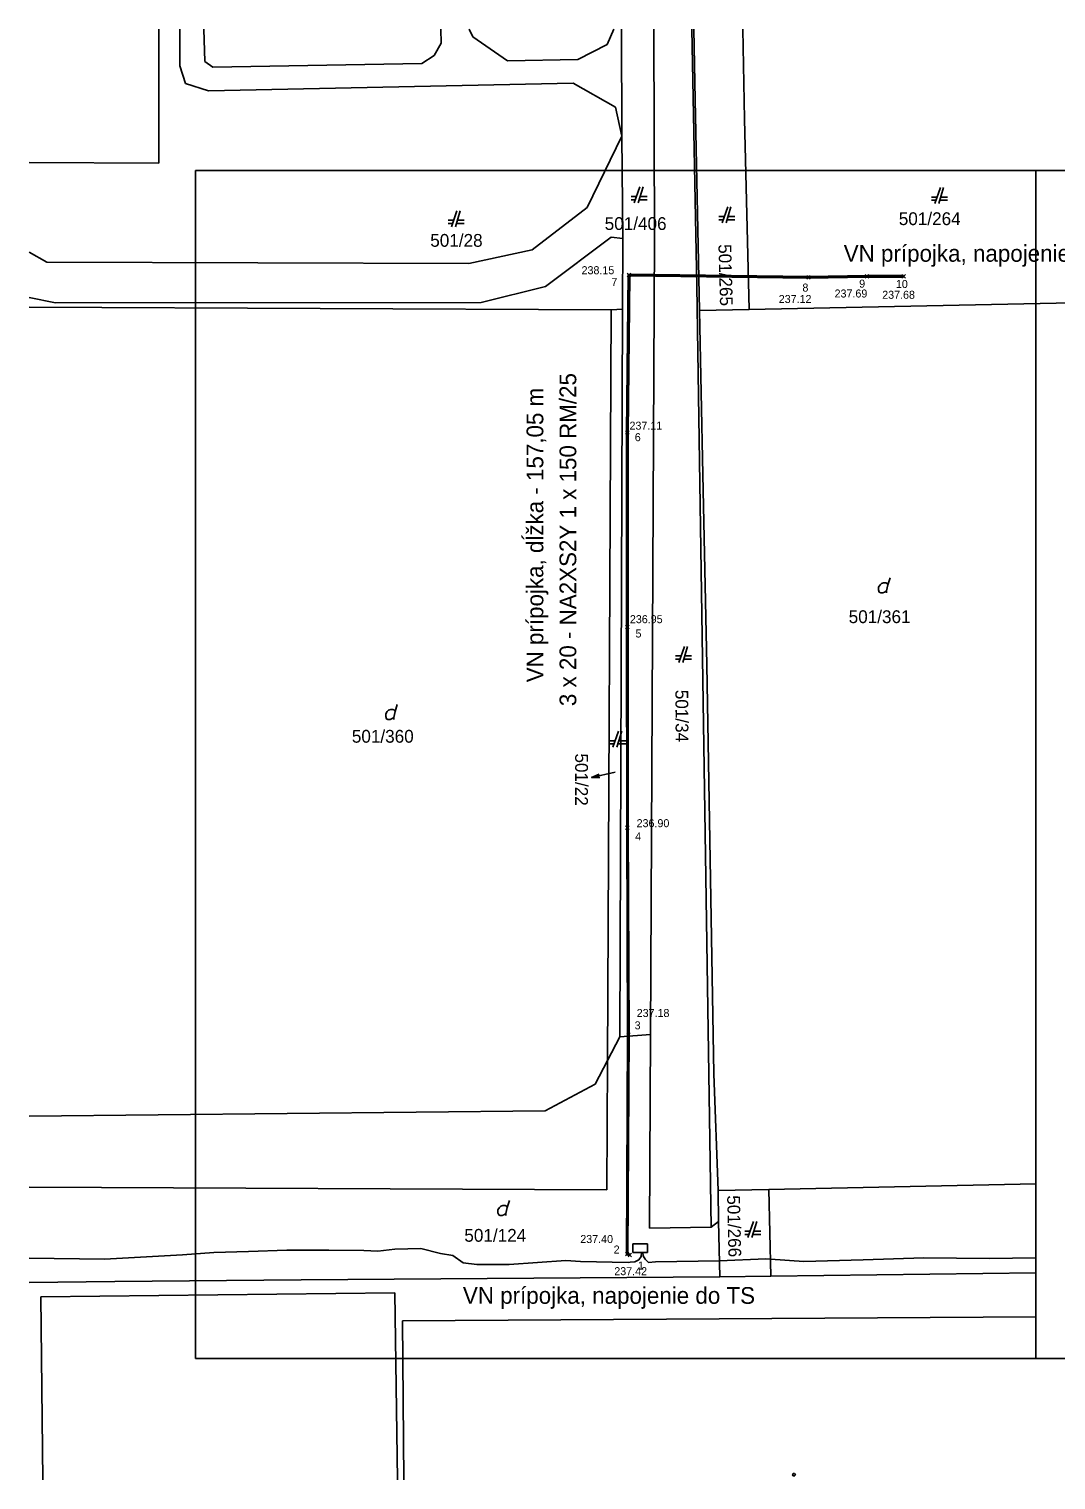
# Model space of a CAD drawing. Extents: x -264024 to -263772, y -1242343 to -1242155.
# Drawn here: x -264023.6 to -263895.2, y -1242343 to -1242161.7 of the extents above; entities that cross this region are included whole.
import ezdxf

# ---------------------------------------------------------------- set-up
doc = ezdxf.new("R2010")
doc.units = 0
for name, color, linetype in [('Default', 7, 'Continuous'), ('Kataster', 7, 'Continuous'), ('Kábelová chránička', 7, 'Continuous'), ('Meraný bod', 7, 'Continuous'), ('Nadmorská výška', 7, 'Continuous'), ('VN kabel', 7, 'Continuous'), ('VN vedenie popis', 7, 'Continuous'), ('Číslo meraného bodu', 7, 'Continuous')]:
    doc.layers.add(name, color=color, linetype=linetype)

msp = doc.modelspace()

# ---------------------------------------------------------------- linework, layer by layer
at = {"layer": 'Default'}
for points in [[(-264002.76, -1242179.33), (-263897.76, -1242179.33), (-263897.76, -1242327.83), (-264002.76, -1242327.83)], [(-263897.76, -1242179.33), (-263792.76, -1242179.33), (-263792.76, -1242327.83), (-263897.76, -1242327.83)]]:
    msp.add_lwpolyline(points, close=True, dxfattribs=at)
at = {"layer": 'Kataster'}
for p, q in [((-264007.36, -1242161.66), (-264007.34, -1242178.42)), ((-264007.34, -1242178.42), (-264007.36, -1242161.66)), ((-264004.74, -1242161.66), (-264004.75, -1242166.25)), ((-264004.75, -1242166.25), (-264004.74, -1242161.66)), ((-264001.62, -1242165.72), (-264001.72, -1242161.66)), ((-264001.72, -1242161.66), (-264001.62, -1242165.72)), ((-263972.1, -1242161.66), (-263972.09, -1242163.43)), ((-263972.09, -1242163.43), (-263972.1, -1242161.66)), ((-263968.11, -1242162.65), (-263968.57, -1242161.66)), ((-263968.57, -1242161.66), (-263968.11, -1242162.65)), ((-263963.77, -1242165.63), (-263968.11, -1242162.65)), ((-263968.11, -1242162.65), (-263963.77, -1242165.63)), ((-263950.51, -1242161.66), (-263951.34, -1242163.61)), ((-263951.34, -1242163.61), (-263950.51, -1242161.66)), ((-263949.49, -1242175.05), (-263949.54, -1242161.66)), ((-263949.54, -1242161.66), (-263949.49, -1242175.05)), ((-263945.5, -1242161.66), (-263945.41, -1242187.87)), ((-263945.41, -1242187.87), (-263945.5, -1242161.66)), ((-263940.75, -1242161.66), (-263940.13, -1242193.8)), ((-263940.13, -1242193.8), (-263940.75, -1242161.66)), ((-263940.34, -1242170.51), (-263940.5, -1242161.66)), ((-263940.5, -1242161.66), (-263940.34, -1242170.51)), ((-263934.15, -1242172.94), (-263934.38, -1242161.66)), ((-263934.38, -1242161.66), (-263934.15, -1242172.94)), ((-263972.93, -1242164.99), (-263974.51, -1242165.96)), ((-263974.51, -1242165.96), (-263972.93, -1242164.99)), ((-263972.09, -1242163.43), (-263972.93, -1242164.99)), ((-263972.93, -1242164.99), (-263972.09, -1242163.43)), ((-263951.34, -1242163.61), (-263955.01, -1242165.46)), ((-263955.01, -1242165.46), (-263951.34, -1242163.61)), ((-264004.75, -1242166.25), (-264004.02, -1242168.46)), ((-264004.02, -1242168.46), (-264004.75, -1242166.25)), ((-264000.63, -1242166.44), (-264001.62, -1242165.72)), ((-264001.62, -1242165.72), (-264000.63, -1242166.44)), ((-263974.51, -1242165.96), (-264000.63, -1242166.44)), ((-264000.63, -1242166.44), (-263974.51, -1242165.96)), ((-263955.01, -1242165.46), (-263963.77, -1242165.63)), ((-263963.77, -1242165.63), (-263955.01, -1242165.46)), ((-264004.02, -1242168.46), (-264001.16, -1242169.4)), ((-264001.16, -1242169.4), (-264004.02, -1242168.46)), ((-264001.16, -1242169.4), (-263955.56, -1242168.43)), ((-263955.56, -1242168.43), (-264001.16, -1242169.4)), ((-263955.56, -1242168.43), (-263950.29, -1242171.43)), ((-263950.29, -1242171.43), (-263955.56, -1242168.43)), ((-263950.29, -1242171.43), (-263949.49, -1242175.05)), ((-263949.49, -1242175.05), (-263950.29, -1242171.43)), ((-263939.79, -1242196.85), (-263940.34, -1242170.51)), ((-263940.34, -1242170.51), (-263939.79, -1242196.85)), ((-263933.6, -1242196.72), (-263934.15, -1242172.94)), ((-263934.15, -1242172.94), (-263933.6, -1242196.72)), ((-263949.49, -1242175.05), (-263953.85, -1242183.98)), ((-263953.85, -1242183.98), (-263949.49, -1242175.05)), ((-263949.38, -1242187.85), (-263949.49, -1242175.05)), ((-263949.49, -1242175.05), (-263949.38, -1242187.85)), ((-264007.34, -1242178.42), (-264023.58, -1242178.33)), ((-264023.58, -1242178.33), (-264007.34, -1242178.42)), ((-263947.66, -1242182.6), (-263948.34, -1242182.6)), ((-263948.34, -1242183), (-263947.8, -1242183)), ((-263947.24, -1242181.4), (-263947.94, -1242183.4)), ((-263947.44, -1242183.4), (-263946.84, -1242181.4)), ((-263947.32, -1242183), (-263946.34, -1242183)), ((-263946.34, -1242182.6), (-263947.2, -1242182.6)), ((-263910.11, -1242182.66), (-263910.79, -1242182.66)), ((-263910.79, -1242183.06), (-263910.25, -1242183.06)), ((-263909.69, -1242181.46), (-263910.39, -1242183.46)), ((-263909.89, -1242183.46), (-263909.29, -1242181.46)), ((-263909.77, -1242183.06), (-263908.79, -1242183.06)), ((-263908.79, -1242182.66), (-263909.65, -1242182.66)), ((-263970.1, -1242184.37), (-263970.8, -1242186.37)), ((-263970.3, -1242186.37), (-263969.7, -1242184.37)), ((-263953.85, -1242183.98), (-263960.7, -1242189.28)), ((-263960.7, -1242189.28), (-263953.85, -1242183.98)), ((-263936.26, -1242183.9), (-263936.96, -1242185.9)), ((-263936.46, -1242185.9), (-263935.86, -1242183.9)), ((-263970.52, -1242185.57), (-263971.2, -1242185.57)), ((-263971.2, -1242185.97), (-263970.66, -1242185.97)), ((-263970.18, -1242185.97), (-263969.2, -1242185.97)), ((-263969.2, -1242185.57), (-263970.06, -1242185.57)), ((-263936.68, -1242185.1), (-263937.36, -1242185.1)), ((-263937.36, -1242185.5), (-263936.82, -1242185.5)), ((-263936.34, -1242185.5), (-263935.36, -1242185.5)), ((-263935.36, -1242185.1), (-263936.22, -1242185.1)), ((-263959.05, -1242193.86), (-263950.83, -1242187.66)), ((-263950.83, -1242187.66), (-263959.05, -1242193.86)), ((-263950.83, -1242187.66), (-263949.38, -1242187.85)), ((-263949.38, -1242187.85), (-263950.83, -1242187.66)), ((-263949.41, -1242196.68), (-263949.38, -1242187.85)), ((-263949.38, -1242187.85), (-263949.41, -1242196.68)), ((-263945.41, -1242187.87), (-263945.92, -1242287.35)), ((-263945.92, -1242287.35), (-263945.41, -1242187.87)), ((-264021.34, -1242190.81), (-264023.58, -1242189.55)), ((-264023.58, -1242189.55), (-264021.34, -1242190.81)), ((-263960.7, -1242189.28), (-263968.63, -1242190.95)), ((-263968.63, -1242190.95), (-263960.7, -1242189.28)), ((-263968.63, -1242190.95), (-264021.34, -1242190.81)), ((-264021.34, -1242190.81), (-263968.63, -1242190.95)), ((-263967.07, -1242195.86), (-263959.05, -1242193.86)), ((-263959.05, -1242193.86), (-263967.07, -1242195.86)), ((-263940.13, -1242193.8), (-263938.35, -1242311.44)), ((-263938.35, -1242311.44), (-263940.13, -1242193.8)), ((-264023.58, -1242195.2), (-264020.26, -1242195.89)), ((-264020.26, -1242195.89), (-264023.58, -1242195.2)), ((-264020.26, -1242195.89), (-263967.07, -1242195.86)), ((-263967.07, -1242195.86), (-264020.26, -1242195.89)), ((-263889.52, -1242195.8), (-263933.6, -1242196.72)), ((-263933.6, -1242196.72), (-263889.52, -1242195.8)), ((-264023.58, -1242196.41), (-263950.84, -1242196.76)), ((-263950.84, -1242196.76), (-264023.58, -1242196.41)), ((-263951.29, -1242290.6), (-263950.84, -1242196.76)), ((-263950.84, -1242196.76), (-263951.29, -1242290.6)), ((-263950.84, -1242196.76), (-263949.41, -1242196.68)), ((-263949.41, -1242196.68), (-263950.84, -1242196.76)), ((-263949.41, -1242196.68), (-263949.74, -1242287.63)), ((-263949.74, -1242287.63), (-263949.41, -1242196.68)), ((-263933.6, -1242196.72), (-263939.79, -1242196.85)), ((-263939.79, -1242196.85), (-263933.6, -1242196.72)), ((-263939.37, -1242217.33), (-263939.79, -1242196.85)), ((-263939.79, -1242196.85), (-263939.37, -1242217.33)), ((-263938.87, -1242241.14), (-263939.37, -1242217.33)), ((-263939.37, -1242217.33), (-263938.87, -1242241.14)), ((-263916.24, -1242231.15), (-263915.97, -1242230.25)), ((-263941.68, -1242238.83), (-263942.38, -1242240.83)), ((-263941.88, -1242240.83), (-263941.28, -1242238.83)), ((-263942.1, -1242240.03), (-263942.78, -1242240.03)), ((-263942.78, -1242240.43), (-263942.24, -1242240.43)), ((-263941.76, -1242240.43), (-263940.78, -1242240.43)), ((-263940.78, -1242240.03), (-263941.64, -1242240.03)), ((-263938.02, -1242292.26), (-263938.87, -1242241.14)), ((-263938.87, -1242241.14), (-263938.02, -1242292.26)), ((-263977.83, -1242246.98), (-263977.56, -1242246.08)), ((-263949.91, -1242249.42), (-263950.61, -1242251.42)), ((-263950.11, -1242251.42), (-263949.51, -1242249.42)), ((-263950.33, -1242250.62), (-263951.01, -1242250.62)), ((-263951.01, -1242251.02), (-263950.47, -1242251.02)), ((-263949.99, -1242251.02), (-263949.01, -1242251.02)), ((-263949.01, -1242250.62), (-263949.87, -1242250.62)), ((-263952.25, -1242255.2), (-263953.27, -1242255.23)), ((-263949.74, -1242287.63), (-263951.29, -1242290.6)), ((-263951.29, -1242290.6), (-263949.74, -1242287.63)), ((-263949.74, -1242287.63), (-263945.92, -1242287.35)), ((-263945.92, -1242287.35), (-263949.74, -1242287.63)), ((-263945.92, -1242287.35), (-263946.05, -1242311.56)), ((-263946.05, -1242311.56), (-263945.92, -1242287.35)), ((-263951.29, -1242290.6), (-263952.82, -1242293.54)), ((-263951.29, -1242290.6), (-263951.37, -1242306.76)), ((-263951.37, -1242306.76), (-263951.29, -1242290.6)), ((-263952.82, -1242293.54), (-263959.09, -1242296.88)), ((-263937.48, -1242306.83), (-263938.02, -1242292.26)), ((-263938.02, -1242292.26), (-263937.48, -1242306.83)), ((-263959.09, -1242296.88), (-264023.58, -1242297.54)), ((-263951.37, -1242306.76), (-264023.58, -1242306.42)), ((-264023.58, -1242306.42), (-263951.37, -1242306.76)), ((-263897.76, -1242306), (-263931.11, -1242306.7)), ((-263931.11, -1242306.7), (-263897.76, -1242306)), ((-263963.81, -1242308.99), (-263963.54, -1242308.09)), ((-263937.48, -1242306.83), (-263931.11, -1242306.7)), ((-263931.11, -1242306.7), (-263937.48, -1242306.83)), ((-263937.4, -1242310.7), (-263937.48, -1242306.83)), ((-263937.48, -1242306.83), (-263937.4, -1242310.7)), ((-263931.11, -1242306.7), (-263930.87, -1242317.54)), ((-263930.87, -1242317.54), (-263931.11, -1242306.7)), ((-263946.05, -1242311.56), (-263938.35, -1242311.44)), ((-263938.35, -1242311.44), (-263946.05, -1242311.56)), ((-263938.35, -1242311.44), (-263937.4, -1242310.7)), ((-263937.4, -1242310.7), (-263938.35, -1242311.44)), ((-263937.4, -1242310.7), (-263937.27, -1242317.62)), ((-263937.27, -1242317.62), (-263937.4, -1242310.7)), ((-263933.46, -1242311.93), (-263934.14, -1242311.93)), ((-263933.04, -1242310.73), (-263933.74, -1242312.73)), ((-263933.24, -1242312.73), (-263932.64, -1242310.73)), ((-263932.14, -1242311.93), (-263933, -1242311.93)), ((-263948.11, -1242314.61), (-263948.11, -1242313.51)), ((-263948.11, -1242313.51), (-263946.29, -1242313.51)), ((-263946.29, -1242313.51), (-263946.29, -1242314.61)), ((-263934.14, -1242312.33), (-263933.6, -1242312.33)), ((-263933.12, -1242312.33), (-263932.14, -1242312.33)), ((-264023.58, -1242315.3), (-264014.13, -1242315.41)), ((-264014.13, -1242315.41), (-264004.4, -1242314.87)), ((-264004.4, -1242314.87), (-264000.5, -1242314.59)), ((-264000.5, -1242314.59), (-263996.15, -1242314.45)), ((-263996.15, -1242314.45), (-263991.36, -1242314.31)), ((-263991.36, -1242314.31), (-263986.12, -1242314.3)), ((-263986.12, -1242314.3), (-263981.72, -1242314.33)), ((-263981.72, -1242314.33), (-263979.98, -1242314.43)), ((-263979.98, -1242314.43), (-263977.86, -1242314.19)), ((-263977.86, -1242314.19), (-263974.61, -1242314.09)), ((-263974.61, -1242314.09), (-263972.17, -1242314.7)), ((-263972.17, -1242314.7), (-263970.63, -1242314.99)), ((-263970.63, -1242314.99), (-263969.31, -1242315.89)), ((-263947.04, -1242314.61), (-263948.11, -1242314.61)), ((-263947.86, -1242315.75), (-263947.37, -1242315.51)), ((-263947.37, -1242315.51), (-263947.08, -1242315.09)), ((-263947.08, -1242315.09), (-263947.04, -1242314.61)), ((-263946.86, -1242314.61), (-263947.04, -1242314.61)), ((-263946.86, -1242314.61), (-263946.83, -1242315.01)), ((-263946.29, -1242314.61), (-263946.86, -1242314.61)), ((-263946.83, -1242315.01), (-263946.58, -1242315.41)), ((-263946.58, -1242315.41), (-263946.15, -1242315.83)), ((-263937.31, -1242315.63), (-263931.52, -1242315.4)), ((-263931.52, -1242315.4), (-263930.92, -1242315.44)), ((-263930.92, -1242315.44), (-263926.77, -1242315.74)), ((-263926.77, -1242315.74), (-263919.34, -1242315.51)), ((-263919.34, -1242315.51), (-263911.76, -1242315.27)), ((-263911.76, -1242315.27), (-263903.58, -1242315.33)), ((-263903.58, -1242315.33), (-263897.76, -1242315.26)), ((-263969.31, -1242315.89), (-263967.63, -1242316.08)), ((-263967.63, -1242316.08), (-263963.59, -1242316.09)), ((-263963.59, -1242316.09), (-263956.5, -1242315.61)), ((-263956.5, -1242315.61), (-263954.68, -1242315.7)), ((-263954.68, -1242315.7), (-263948.7, -1242315.83)), ((-263948.7, -1242315.83), (-263948.46, -1242315.82)), ((-263948.46, -1242315.82), (-263947.86, -1242315.75)), ((-263946.15, -1242315.83), (-263945.29, -1242315.78)), ((-263945.29, -1242315.78), (-263937.31, -1242315.63)), ((-263930.87, -1242317.54), (-263897.76, -1242317.13)), ((-263897.76, -1242317.13), (-263930.87, -1242317.54)), ((-264012.87, -1242318.24), (-264023.58, -1242318.34)), ((-264023.58, -1242318.34), (-264012.87, -1242318.24)), ((-263989.58, -1242318.02), (-264012.87, -1242318.24)), ((-264012.87, -1242318.24), (-263989.58, -1242318.02)), ((-263937.27, -1242317.62), (-263989.58, -1242318.02)), ((-263989.58, -1242318.02), (-263937.27, -1242317.62)), ((-263930.87, -1242317.54), (-263937.27, -1242317.62)), ((-263937.27, -1242317.62), (-263930.87, -1242317.54)), ((-263977.86, -1242319.64), (-264022.1, -1242320.14)), ((-264022.1, -1242320.14), (-264021.85, -1242343.03)), ((-263977.54, -1242343.03), (-263977.86, -1242319.64)), ((-263976.89, -1242323.14), (-263897.76, -1242322.62)), ((-263897.76, -1242322.62), (-263976.89, -1242323.14)), ((-263976.76, -1242343.03), (-263976.89, -1242323.14)), ((-263976.89, -1242323.14), (-263976.76, -1242343.03))]:
    msp.add_line(p, q, dxfattribs=at)
for points in [[(-263916.42, -1242232.14), (-263916.42, -1242231.87), (-263916.24, -1242231.15), (-263916.33, -1242230.97), (-263916.51, -1242230.88), (-263916.78, -1242230.88), (-263917.05, -1242230.97), (-263917.23, -1242231.15), (-263917.41, -1242231.42), (-263917.41, -1242231.78), (-263917.32, -1242232.05), (-263917.14, -1242232.14), (-263916.87, -1242232.14), (-263916.69, -1242232.05), (-263916.42, -1242231.87)], [(-263978.01, -1242247.97), (-263978.01, -1242247.7), (-263977.83, -1242246.98), (-263977.92, -1242246.8), (-263978.1, -1242246.71), (-263978.37, -1242246.71), (-263978.64, -1242246.8), (-263978.82, -1242246.98), (-263979, -1242247.25), (-263979, -1242247.61), (-263978.91, -1242247.88), (-263978.73, -1242247.97), (-263978.46, -1242247.97), (-263978.28, -1242247.88), (-263978.01, -1242247.7)], [(-263950.35, -1242254.55), (-263953.27, -1242255.23), (-263952.34, -1242254.81)], [(-263963.99, -1242309.98), (-263963.99, -1242309.71), (-263963.81, -1242308.99), (-263963.9, -1242308.81), (-263964.08, -1242308.72), (-263964.35, -1242308.72), (-263964.62, -1242308.81), (-263964.8, -1242308.99), (-263964.98, -1242309.26), (-263964.98, -1242309.62), (-263964.89, -1242309.89), (-263964.71, -1242309.98), (-263964.44, -1242309.98), (-263964.26, -1242309.89), (-263963.99, -1242309.71)]]:
    msp.add_lwpolyline(points, dxfattribs=at)
msp.add_lwpolyline([(-263927.9, -1242342.23), (-263927.81, -1242342.38), (-263927.9, -1242342.53), (-263928.08, -1242342.53), (-263928.17, -1242342.38), (-263928.08, -1242342.23)], close=True, dxfattribs=at)
at = {"layer": 'Kábelová chránička'}
for points in [[(-263948.53, -1242315), (-263948.93, -1242314.84), (-263948.77, -1242287.36), (-263948.89, -1242261.47), (-263948.92, -1242236.41), (-263948.92, -1242212.09), (-263948.71, -1242192.31), (-263926.18, -1242192.61), (-263918.86, -1242192.47), (-263914.29, -1242192.49)], [(-263948.45, -1242314.82), (-263948.73, -1242314.7), (-263948.57, -1242287.36), (-263948.7, -1242261.47), (-263948.72, -1242236.41), (-263948.72, -1242212.09), (-263948.51, -1242192.52), (-263926.18, -1242192.81), (-263918.86, -1242192.67), (-263914.29, -1242192.68)]]:
    msp.add_lwpolyline(points, dxfattribs=at)
at = {"layer": 'Meraný bod'}
for p, q in [((-263948.61, -1242192.42), (-263948.61, -1242192.42)), ((-263926.18, -1242192.71), (-263926.18, -1242192.71)), ((-263918.86, -1242192.57), (-263918.86, -1242192.57)), ((-263914.29, -1242192.58), (-263914.29, -1242192.58)), ((-263948.82, -1242212.09), (-263948.82, -1242212.09)), ((-263948.82, -1242236.41), (-263948.82, -1242236.41)), ((-263948.79, -1242261.47), (-263948.79, -1242261.47)), ((-263948.67, -1242287.36), (-263948.67, -1242287.36)), ((-263948.83, -1242314.77), (-263948.83, -1242314.77)), ((-263948.49, -1242314.91), (-263948.49, -1242314.91))]:
    msp.add_line(p, q, dxfattribs=at)
for points in [[(-263948.83, -1242192.19), (-263948.38, -1242192.64)], [(-263948.83, -1242192.64), (-263948.38, -1242192.19)], [(-263926.4, -1242192.48), (-263925.95, -1242192.93)], [(-263926.4, -1242192.93), (-263925.95, -1242192.48)], [(-263919.08, -1242192.34), (-263918.63, -1242192.79)], [(-263919.08, -1242192.79), (-263918.63, -1242192.34)], [(-263914.52, -1242192.36), (-263914.07, -1242192.81)], [(-263914.52, -1242192.81), (-263914.07, -1242192.36)], [(-263949.04, -1242211.87), (-263948.59, -1242212.32)], [(-263949.04, -1242212.32), (-263948.59, -1242211.87)], [(-263949.05, -1242236.18), (-263948.6, -1242236.63)], [(-263949.05, -1242236.63), (-263948.6, -1242236.18)], [(-263949.02, -1242261.25), (-263948.57, -1242261.7)], [(-263949.02, -1242261.7), (-263948.57, -1242261.25)], [(-263948.89, -1242287.14), (-263948.44, -1242287.59)], [(-263948.89, -1242287.59), (-263948.44, -1242287.14)], [(-263949.06, -1242314.55), (-263948.61, -1242315)], [(-263949.06, -1242315), (-263948.61, -1242314.55)], [(-263948.72, -1242314.69), (-263948.27, -1242315.14)], [(-263948.72, -1242315.14), (-263948.27, -1242314.69)]]:
    msp.add_lwpolyline(points, dxfattribs=at)
at = {"layer": 'VN kabel'}
for p, q in [((-263918.86, -1242192.57), (-263914.29, -1242192.58)), ((-263948.49, -1242314.91), (-263948.83, -1242314.77))]:
    msp.add_line(p, q, dxfattribs=at)
msp.add_lwpolyline([(-263948.83, -1242314.77), (-263948.67, -1242287.36), (-263948.79, -1242261.47), (-263948.82, -1242236.41), (-263948.82, -1242212.09), (-263948.61, -1242192.42), (-263926.18, -1242192.71), (-263918.86, -1242192.57)], dxfattribs=at)

# ---------------------------------------------------------------- texts
at = {"layer": 'Kataster'}
for s, p in [('501/264', (-263914.89, -1242186.17)), ('501/406', (-263951.64, -1242186.78)), ('501/28', (-263973.44, -1242188.88)), ('501/361', (-263921.15, -1242235.92)), ('501/360', (-263983.24, -1242250.87)), ('501/124', (-263969.18, -1242313.25))]:
    msp.add_text(s, height=1.6, dxfattribs=at).set_placement(p)
for s, rotation, p in [('501/265', 271.5247, (-263937.43, -1242188.57)), ('501/34', 270.3788, (-263942.81, -1242244.26)), ('501/22', 269.9777, (-263955.33, -1242252.21)), ('501/266', 271.2382, (-263936.34, -1242307.46))]:
    msp.add_text(s, height=1.6, rotation=rotation, dxfattribs=at).set_placement(p)
at = {"layer": 'Nadmorská výška'}
for s, p in [('238.15', (-263954.53, -1242192.31)), ('237.12', (-263929.89, -1242195.91)), ('237.69', (-263922.91, -1242195.22)), ('237.68', (-263916.96, -1242195.38)), ('237.11', (-263948.54, -1242211.74)), ('236.95', (-263948.49, -1242235.93)), ('236.90', (-263947.65, -1242261.43)), ('237.18', (-263947.64, -1242285.16)), ('237.40', (-263954.69, -1242313.41)), ('237.42', (-263950.44, -1242317.43))]:
    msp.add_text(s, height=1, dxfattribs=at).set_placement(p)
at = {"layer": 'VN vedenie popis'}
for s, rotation, p in [('VN prípojka, napojenie do budovy', 360, (-263921.77, -1242190.75)), ('3 x 20 - NA2XS2Y 1 x 150 RM/25', 90, (-263955.19, -1242246.3)), ('VN prípojka, dĺžka - 157,05 m', 90, (-263959.31, -1242243.32)), ('VN prípojka, napojenie do TS', 360, (-263969.36, -1242321.01))]:
    msp.add_text(s, height=2.09, rotation=rotation, dxfattribs=at).set_placement(p)
at = {"layer": 'Číslo meraného bodu'}
for s, p in [('7', (-263950.8, -1242193.77)), ('8', (-263926.93, -1242194.48)), ('9', (-263919.84, -1242193.99)), ('10', (-263915.25, -1242194.03)), ('6', (-263947.88, -1242213.18)), ('5', (-263947.79, -1242237.72)), ('4', (-263947.83, -1242263.08)), ('3', (-263947.9, -1242286.7)), ('2', (-263950.52, -1242314.72)), ('1', (-263947.49, -1242316.72))]:
    msp.add_text(s, height=1, dxfattribs=at).set_placement(p)

doc.saveas('drawing.dxf')
